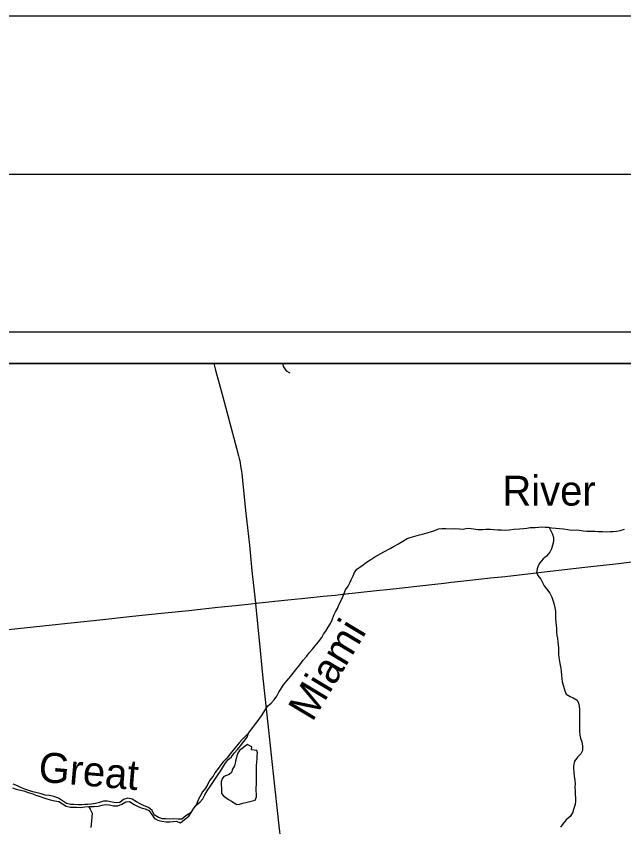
# Model space of a CAD drawing. Extents: x 0 to 34, y -5.4 to 22.
# Drawn here: x 5.117 to 7.042, y 19.432 to 22 of the extents above; entities that cross this region are included whole.
import ezdxf

# ---------------------------------------------------------------- set-up
doc = ezdxf.new("R2010")
doc.units = 0
for name, color, linetype in [('GM_X_County_Road', 7, 'Continuous'), ('GM_X_Minor_Lake', 7, 'Continuous'), ('GM_X_Minor_River', 7, 'Continuous'), ('GM_X_Minor_River_Text', 7, 'Continuous'), ('GM_X_Rail_Line', 7, 'Continuous'), ('GM_X_State_Route', 7, 'Continuous'), ('SH_Border', 7, 'Continuous'), ('SH_Cut_Line', 7, 'Continuous'), ('SH_Data', 7, 'Continuous')]:
    doc.layers.add(name, color=color, linetype=linetype)

msp = doc.modelspace()

# ---------------------------------------------------------------- linework, layer by layer
at = {"layer": 'GM_X_County_Road'}
for points in [[(5.8744, 20.1399), (5.8793, 20.1404), (5.8875, 20.1412), (5.9364, 20.1462), (5.9883, 20.1516), (6.0316, 20.1562), (6.0891, 20.1622), (6.1268, 20.166), (6.1515, 20.1687), (6.2003, 20.1739), (6.2578, 20.1802), (6.301, 20.185), (6.4338, 20.1999), (6.4721, 20.2041), (6.4949, 20.2068), (6.5258, 20.2103), (6.582, 20.2164), (6.6191, 20.2203), (6.6659, 20.2251), (6.7457, 20.2342), (6.7809, 20.2383), (6.8359, 20.2444), (6.8815, 20.2497), (6.9278, 20.2553), (7.025, 20.2661), (7.0994, 20.2752)], [(4.6127, 20.0058), (4.6274, 20.0077), (4.6542, 20.0107), (4.6851, 20.0139), (4.7308, 20.0187), (4.7554, 20.0212), (4.8154, 20.0269), (4.902, 20.0362), (4.9508, 20.0418), (5.0323, 20.0506), (5.0923, 20.0569), (5.201, 20.0686), (5.3005, 20.0791), (5.3821, 20.0878), (5.4847, 20.0988), (5.5768, 20.1084), (5.6305, 20.114), (5.6639, 20.1176), (5.7554, 20.1273), (5.811, 20.1332), (5.8611, 20.1385), (5.8744, 20.1399)]]:
    msp.add_lwpolyline(points, dxfattribs=at)
at = {"layer": 'GM_X_Minor_Lake'}
for points in [[(5.8797, 19.648), (5.8797, 19.6485), (5.8799, 19.6576), (5.8808, 19.6659), (5.8794, 19.6735), (5.8707, 19.6748), (5.862, 19.6757), (5.8636, 19.6852), (5.8569, 19.6883), (5.849, 19.693), (5.8417, 19.6878), (5.8325, 19.6796), (5.8241, 19.674), (5.819, 19.6653), (5.8154, 19.6563), (5.8138, 19.6476), (5.8118, 19.6396), (5.8109, 19.6332), (5.8085, 19.6249), (5.8023, 19.6143), (5.7991, 19.6041), (5.7911, 19.5974), (5.7829, 19.5942)], [(5.7829, 19.5942), (5.775, 19.5912), (5.7692, 19.5837), (5.7661, 19.5739), (5.7663, 19.564), (5.7669, 19.5553), (5.7668, 19.5458), (5.767, 19.5375), (5.773, 19.5294), (5.782, 19.5239), (5.7895, 19.5185), (5.7985, 19.5131), (5.8071, 19.5076), (5.8158, 19.5025), (5.8241, 19.5036), (5.8344, 19.5068), (5.8447, 19.5089), (5.8564, 19.5122), (5.8652, 19.5136), (5.8736, 19.5157), (5.8783, 19.5263), (5.8776, 19.5354), (5.877, 19.5453), (5.8775, 19.5764), (5.878, 19.5859), (5.8778, 19.5927), (5.8775, 19.6014), (5.878, 19.6102), (5.8783, 19.6272), (5.8788, 19.6356), (5.8797, 19.648)]]:
    msp.add_lwpolyline(points, dxfattribs=at)
at = {"layer": 'GM_X_Minor_River'}
for points in [[(5.9601, 20.9), (5.9636, 20.889), (5.9717, 20.876), (5.9841, 20.8701)], [(5.8529, 19.7282), (5.8661, 19.7462), (5.8754, 19.759), (5.8866, 19.7725), (5.8959, 19.7868), (5.904, 19.8003), (5.9133, 19.8138), (5.9249, 19.8239), (5.9341, 19.8336), (5.9423, 19.846), (5.9489, 19.8581), (5.9547, 19.8679), (5.9636, 19.8818), (5.9737, 19.8945), (5.9868, 19.9095), (5.9976, 19.9226), (6.0057, 19.9331), (6.0154, 19.9451), (6.0255, 19.9598), (6.037, 19.9721), (6.0448, 19.9826), (6.0552, 19.995), (6.0641, 20.0051), (6.0745, 20.0175), (6.0845, 20.0318), (6.0904, 20.0419), (6.0974, 20.0521), (6.1051, 20.0641), (6.1125, 20.0761), (6.118, 20.0871), (6.1231, 20.1022), (6.1278, 20.1131), (6.1348, 20.1236), (6.1392, 20.1346), (6.1439, 20.1447), (6.1505, 20.1579), (6.1545, 20.1685), (6.1604, 20.1828), (6.1685, 20.1945), (6.1732, 20.2043), (6.1783, 20.2148), (6.1838, 20.2269), (6.1889, 20.2378), (6.1958, 20.248), (6.2058, 20.2543), (6.2158, 20.2617), (6.2265, 20.2699), (6.2403, 20.2788), (6.2525, 20.2869), (6.2625, 20.2921), (6.272, 20.2977), (6.2816, 20.3028), (6.3018, 20.3135), (6.314, 20.3209), (6.3255, 20.3276), (6.3416, 20.3372), (6.3557, 20.345), (6.3653, 20.3486), (6.3793, 20.353), (6.3946, 20.3569), (6.4041, 20.359), (6.4185, 20.363), (6.4322, 20.3669), (6.4429, 20.3706), (6.4547, 20.3757), (6.465, 20.3774), (6.4775, 20.3769), (6.4945, 20.3762), (6.5066, 20.3764), (6.5207, 20.3755), (6.5324, 20.3753), (6.5457, 20.3777), (6.5578, 20.3772), (6.5805, 20.3738), (6.5941, 20.3736), (6.6044, 20.3745), (6.6195, 20.3747), (6.6298, 20.3738), (6.6426, 20.3732), (6.6529, 20.3726), (6.6654, 20.3721), (6.6794, 20.373), (6.6931, 20.3751), (6.7109, 20.3755), (6.7242, 20.3769), (6.7348, 20.3782), (6.7447, 20.3796), (6.7606, 20.3797), (6.772, 20.3807), (6.7822, 20.3817), (6.7921, 20.3811), (6.803, 20.381), (6.8129, 20.3793), (6.8265, 20.3779), (6.8382, 20.377), (6.8511, 20.376), (6.8647, 20.3735), (6.8753, 20.3719), (6.8905, 20.3724), (6.9007, 20.3718), (6.9135, 20.3694)], [(6.8051, 20.3806), (6.809, 20.3717), (6.816, 20.3587), (6.8185, 20.3484), (6.8194, 20.3355), (6.8162, 20.3242), (6.8122, 20.3121), (6.8075, 20.3015), (6.7971, 20.2892), (6.7867, 20.281), (6.7759, 20.2686), (6.7709, 20.2588), (6.7677, 20.249), (6.7656, 20.2377), (6.7693, 20.2281), (6.7789, 20.2162), (6.7837, 20.2055), (6.7896, 20.1955), (6.7963, 20.186), (6.8074, 20.1721), (6.8133, 20.1591), (6.8173, 20.1496), (6.8213, 20.1362), (6.823, 20.1259), (6.8251, 20.1145), (6.8253, 20.1012), (6.8255, 20.0914), (6.8261, 20.0803), (6.8271, 20.0708), (6.8281, 20.0602), (6.8287, 20.0507), (6.83, 20.0374), (6.8318, 20.0279), (6.8331, 20.018), (6.8341, 20.0085), (6.8347, 19.9986), (6.8346, 19.9891), (6.8352, 19.9792), (6.8362, 19.9686), (6.8379, 19.9557), (6.84, 19.9442), (6.8425, 19.9343), (6.8434, 19.9241), (6.844, 19.9119), (6.8454, 19.9016), (6.8463, 19.8906), (6.8503, 19.8769), (6.8554, 19.8631), (6.8594, 19.8525), (6.8718, 19.8447), (6.8816, 19.8403), (6.8936, 19.8333), (6.8984, 19.8238), (6.9001, 19.8142), (6.9015, 19.8025), (6.9011, 19.7804), (6.9013, 19.7679), (6.9012, 19.7577), (6.9013, 19.7448), (6.9016, 19.7349), (6.9029, 19.7223), (6.9046, 19.7128), (6.9086, 19.7006), (6.9111, 19.6877), (6.9105, 19.6733), (6.9058, 19.6631), (6.8958, 19.653), (6.8857, 19.6395), (6.8821, 19.6255), (6.8819, 19.616), (6.8829, 19.6038), (6.8846, 19.592), (6.8867, 19.578), (6.8873, 19.5681), (6.8871, 19.5571), (6.8873, 19.5442), (6.8879, 19.5339), (6.8888, 19.5225), (6.8887, 19.513), (6.8874, 19.5028), (6.8834, 19.49), (6.879, 19.4764), (6.8713, 19.464), (6.8586, 19.4539), (6.8501, 19.4423), (6.8416, 19.4302)], [(6.9135, 20.3694), (6.9245, 20.3684), (6.9397, 20.3686), (6.9499, 20.3684), (6.9605, 20.3679), (6.9753, 20.3673), (6.9862, 20.3663), (6.9984, 20.3673), (7.0082, 20.3675), (7.0189, 20.3681), (7.0303, 20.371), (7.044, 20.3753)], [(5.8529, 19.7282), (5.8333, 19.7095), (5.8229, 19.6975), (5.8125, 19.6848), (5.8044, 19.6751), (5.7947, 19.6627), (5.7835, 19.6496), (5.7727, 19.6376), (5.7654, 19.6278), (5.7576, 19.6173), (5.7464, 19.6031), (5.7406, 19.5925), (5.7294, 19.579), (5.7243, 19.567), (5.7161, 19.5546), (5.7072, 19.5422), (5.6994, 19.529), (5.6932, 19.5169), (5.6869, 19.5007)], [(5.757, 19.5976), (5.7635, 19.6077), (5.7705, 19.619), (5.7783, 19.6322), (5.7876, 19.6442), (5.7987, 19.6539), (5.8072, 19.6648), (5.8177, 19.6771), (5.8269, 19.6884), (5.8377, 19.7023), (5.8482, 19.7154), (5.8529, 19.7282)], [(5.6869, 19.5007), (5.6999, 19.5111), (5.7077, 19.5209), (5.7143, 19.5333), (5.7217, 19.5461), (5.731, 19.5596), (5.7399, 19.5724), (5.748, 19.5844), (5.757, 19.5976)], [(5.1045, 19.5552), (5.1169, 19.5509), (5.1305, 19.548), (5.1404, 19.5456), (5.1547, 19.5408), (5.1694, 19.536), (5.1792, 19.5324), (5.189, 19.5285), (5.2007, 19.5249), (5.2105, 19.5217), (5.2241, 19.5177), (5.2388, 19.5137), (5.2516, 19.512), (5.2633, 19.5042), (5.2753, 19.4972), (5.2889, 19.4943), (5.2995, 19.4941), (5.3093, 19.4936), (5.3196, 19.4934), (5.334, 19.4947), (5.3488, 19.4964), (5.3632, 19.4966), (5.3765, 19.4975), (5.3886, 19.5007), (5.3989, 19.5025), (5.4125, 19.5011), (5.4254, 19.4983), (5.439, 19.4984), (5.4516, 19.5036), (5.4635, 19.5106), (5.4756, 19.5123), (5.4899, 19.5026), (5.5011, 19.4971), (5.5124, 19.4924), (5.5249, 19.4884), (5.5369, 19.4833), (5.5462, 19.4706), (5.5544, 19.4576), (5.5649, 19.4529), (5.5777, 19.4492), (5.5913, 19.4471), (5.6046, 19.4473), (5.6141, 19.4491), (5.6236, 19.4493), (5.6375, 19.4449), (5.6502, 19.4546), (5.664, 19.465), (5.6706, 19.4771)], [(5.6706, 19.4771), (5.6542, 19.4663), (5.6419, 19.4559), (5.6297, 19.456), (5.6165, 19.457), (5.6028, 19.4565), (5.59, 19.4567), (5.5801, 19.4572), (5.5673, 19.4608), (5.5542, 19.4701), (5.5475, 19.4835), (5.5359, 19.4932), (5.5224, 19.4987), (5.5096, 19.5046), (5.4976, 19.5112), (5.4837, 19.5198), (5.4708, 19.523), (5.4567, 19.5183), (5.4452, 19.5086), (5.4331, 19.5073), (5.4206, 19.5097), (5.4059, 19.513), (5.393, 19.5128), (5.3804, 19.5085), (5.3679, 19.5052), (5.355, 19.5035), (5.3436, 19.5026), (5.3337, 19.5023), (5.3242, 19.5017), (5.3129, 19.5015), (5.2992, 19.5021), (5.2886, 19.5027), (5.2762, 19.5055), (5.2638, 19.514), (5.2503, 19.5226), (5.236, 19.5278), (5.2224, 19.5306), (5.2087, 19.5324), (5.1959, 19.5363), (5.1827, 19.5392), (5.1695, 19.5428), (5.1567, 19.5472), (5.1435, 19.5512), (5.1337, 19.5551), (5.1205, 19.5614), (5.107, 19.5669)], [(5.3458, 19.4961), (5.3513, 19.4873), (5.3576, 19.4746), (5.3562, 19.4618), (5.3557, 19.4496), (5.354, 19.439), (5.3535, 19.4292)], [(5.6706, 19.4771), (5.678, 19.4891), (5.6869, 19.5007)]]:
    msp.add_lwpolyline(points, dxfattribs=at)
at = {"layer": 'GM_X_Rail_Line'}
msp.add_lwpolyline([(8.9, 19.2127), (8.9, 20.9), (3.5133, 20.9), (3.5122, 20.8763), (3.4778, 20.1697), (3.46, 19.8188), (3.4303, 19.2337), (3.4301, 19.2311), (3.4297, 19.2264), (3.3865, 18.7781), (3.3669, 18.5872), (3.5131, 18.6037), (4.7505, 18.7432), (5.0255, 18.7742), (5.096, 18.7806), (5.378, 18.814), (5.7313, 18.8595), (5.7334, 18.8597), (6.0045, 18.8908), (6.4496, 18.9373), (6.6792, 18.9603), (6.9054, 18.9823), (7.2315, 19.0156), (8.5201, 19.1691)], close=True, dxfattribs=at)
at = {"layer": 'GM_X_State_Route'}
for points in [[(5.7423, 20.9), (5.748, 20.8788), (5.771, 20.7939), (5.8146, 20.6319), (5.8213, 20.6071), (5.8231, 20.5992), (5.825, 20.5908), (5.8264, 20.5839), (5.8278, 20.5755), (5.8297, 20.5634), (5.8311, 20.5515), (5.8436, 20.4342), (5.8553, 20.324), (5.8637, 20.2433), (5.8714, 20.1687)], [(5.8714, 20.1687), (5.8744, 20.1399), (5.8745, 20.1384), (5.886, 20.0226), (5.8984, 19.9027), (5.9152, 19.7476), (5.9312, 19.6), (5.9491, 19.435), (5.9537, 19.3905), (5.9544, 19.3846)]]:
    msp.add_lwpolyline(points, dxfattribs=at)
at = {"layer": 'SH_Border'}
msp.add_lwpolyline([(1.5, 21.5), (33.5, 21.5), (33.5, 0.5), (1.5, 0.5)], close=True, dxfattribs=at)
at = {"layer": 'SH_Cut_Line'}
msp.add_lwpolyline([(0, 0), (34, 0), (34, 22), (0, 22)], close=True, dxfattribs=at)
at = {"layer": 'SH_Data'}
for p, q in [((2, 21), (9, 21)), ((2.1, 20.9), (8.9, 20.9))]:
    msp.add_line(p, q, dxfattribs=at)

# ---------------------------------------------------------------- texts
at = {"layer": 'GM_X_Minor_River_Text'}
for s, rotation, p in [('River', 0.0298, (6.6571, 20.4493)), ('Miami', 59.0259, (6.0548, 19.7616)), ('Great', 355.039, (5.1847, 19.5753))]:
    msp.add_text(s, height=0.09471, rotation=rotation, dxfattribs=at).set_placement(p)

doc.saveas('drawing.dxf')
